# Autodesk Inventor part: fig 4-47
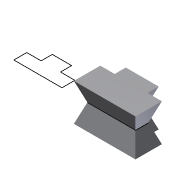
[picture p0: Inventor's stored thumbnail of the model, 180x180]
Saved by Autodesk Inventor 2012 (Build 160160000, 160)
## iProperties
Created: 2004-05
Part Number: fig 4-47
Document SubType Name: Modeling
Designer: CADCIM Technologies
Manufacturer: Standard
Standards Organization: Custom
Density: 1 g/cm^3
Material: Default
Author: CADCIM Technologies
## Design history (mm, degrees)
sketch "Sketch1"
  geometry: L1 (31.783, 34.561)-(31.783, 22.933); L2 (31.783, 22.933)-(16.796, 22.933); L3 (16.796, 22.933)-(16.796, 9.496); L4 (16.796, 9.496)-(66.925, 9.496); L5 (66.925, 9.496)-(66.925, 22.933); L6 (66.925, 22.933)-(51.938, 22.933); L7 (51.938, 22.933)-(51.938, 34.561); L8 (51.938, 34.561)-(31.783, 34.561); L9 (-45.013, 34.561)-(-45.013, 22.933); L10 (-45.013, 22.933)-(-60, 22.933); L11 (-60, 22.933)-(-60, 9.496); L12 (-60, 9.496)-(-9.871, 9.496); L13 (-9.871, 9.496)-(-9.871, 22.933); L14 (-9.871, 22.933)-(-24.858, 22.933); L15 (-24.858, 22.933)-(-24.858, 34.561); L16 (-24.858, 34.561)-(-45.013, 34.561)
  constraints: 32 end point, 10 parallel, 4 equal length, 2 collinear, 2 perpendicular, 2 vertical
extrude "Extrusion2" new body sketch "Sketch1" stored distance "d2" = 38.75; taper "d3" = 20 deg
body "Solid2"
